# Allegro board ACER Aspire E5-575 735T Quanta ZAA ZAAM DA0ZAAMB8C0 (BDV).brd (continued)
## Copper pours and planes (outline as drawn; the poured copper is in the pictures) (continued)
SLEEVE on IN1 (solid shape): 206.3,27.2 206.3,24.66 206.18,24.53 205.42,24.53 205.16,24.78 205.16,27.2 205.29,27.32 206.18,27.32
SLEEVE_R on BOTTOM (solid shape): 206.56,24.02 206.56,22.63 206.43,22.5 205.42,22.5 205.29,22.63 205.29,24.15 206.43,24.15
SLEEVE_R on BOTTOM (solid shape): 210.29,15.38 210.35,15.38 210.39,15.37 210.4,15.33 210.4,15.3 211.59,15.3 211.62,15.29 211.64,15.25 211.64,15.05 211.62,15.01 211.59,15 210.4,15 210.4,14.8 211.59,14.8 211.62,14.79 211.64,14.75 211.64,14.55 211.62,14.51 211.59,14.5 210.4,14.5 210.4,14.3 211.59,14.3 211.62,14.29 211.64,14.25 211.64,14.05 211.62,14.01 211.59,14 210.4,14 210.4,13.99 209.1,13.99 208.84,14.24 208.84,15.13 209.1,15.39 210.29,15.39
SLEEVE_R on IN1 (solid shape): 206.69,23.51 206.69,21.74 206.56,21.61 205.67,21.61 205.67,23.51 205.8,23.64 206.56,23.64
SLEEVE_R on IN1 (solid shape): 209.86,15.26 209.86,14.24 209.73,14.12 208.46,14.12 208.08,14.5 208.08,15.13 208.46,15.51 209.61,15.51
SM_RCOMP_1 on IN1 (solid shape): 131.76,105.42 131.84,105.37 131.86,105.28 131.85,105.09 131.94,104.92 131.97,104.85 131.84,104.53 131.97,104.2 131.94,104.13 131.85,103.8 132.06,103.54 132.07,103.54 132.29,103.32 132.29,102.61 132.05,102.37 131.79,102.37 131.61,102.55 131.61,104.34 131.62,104.7 131.32,104.9 131.3,104.9 131.16,105.03 131.16,105.29 131.29,105.42
SYSTEM_AGND on TOP (solid shape): 57.54,40.07 57.54,38.39 57.49,38.2 57.54,38 57.54,37.28 57.37,37.12 57.06,37.12 56.85,37.39 56.85,37.59 56.84,37.6 56.84,37.73 56.58,37.99 56.3,37.99 56.18,38.1 56.18,39.65 55.05,40.79 55.05,41.24 55.12,41.32 56.29,41.32
TERM9 on TOP (solid shape): 26.07,92.53 26.07,78.46 25.91,78.3 25.05,78.3 24.87,78.48 24.87,89.33 24.24,89.96 24.24,92.86 24.39,93.01 25.58,93.01
TERM9 on BOTTOM (solid shape): 28.58,94.61 28.58,92.4 28.43,92.25 24.47,92.25 24.24,92.48 24.24,93.34 25.66,94.76 28.43,94.76
TP_PWR on TOP (solid shape): 116.74,171.34 119.83,171.34 120.01,171.16 120.01,169.92 119.84,169.74 118.52,169.74 118.21,170.06 118.19,170.07 118.18,170.07 118.16,170.09 117.66,170.09 117.65,170.07 116.39,170.07 116.13,169.82 115.63,169.82 115.4,170.05 115.4,171.42 115.45,171.47 116.62,171.47
TP_PWR on BOTTOM (solid shape): 119.36,170.63 119.36,170.35 119.31,170.3 119.31,170.05 120.14,169.22 119.96,169.04 119.15,169.85 118.98,169.68 119.78,168.87 119.6,168.69 118.78,169.52 118.72,169.52 118.27,169.97 118.27,170.14 118.75,170.62 118.75,170.61 118.88,170.73 119.26,170.73
USBPWR0 on TOP (solid shape): 23.86,26.18 23.86,26.05 23.3,25.5 23.3,24.15 21.52,22.37 21.27,22.37 20.63,21.74 19.82,21.74 19.78,21.78 19.67,21.86 19.53,21.89 19.52,21.89 19.47,21.93 19.47,21.95 19.39,22.1 19.26,22.2 19.23,22.21 19.23,22.55 19.28,22.63 19.37,22.64 19.87,23.04 19.31,23.35 19.22,23.35 19.17,23.44 19.17,23.95 19.17,24.26 19.08,24.34 19.08,24.36 19.07,24.36 19.07,24.5 19.1,24.53 19.45,24.53 19.45,24.52 20.69,24.52 20.69,24.53 21.39,24.53 21.52,24.66 21.52,24.81 21.53,24.91 21.52,25.01 21.52,25.8 22,26.28 23.75,26.28
USBPWR0 on IN2 (solid shape): outline of 417 points within 13.75,15.39 22.15,24.29
USBPWR1 on TOP (solid shape): 22.41,39.26 22.41,37.61 22.15,37.36 21.01,37.36 20.89,37.23 20.88,37.23 20.61,36.96 20.6,36.95 20.31,36.63 20.44,36.23 20.44,36.17 20.41,36.13 20,35.72 19.59,35.72 19.47,35.6 19.37,35.39 19.4,35.16 19.41,35.14 19.4,35.11 19.11,34.82 14.92,34.82 14.76,34.67 14.45,34.67 13.79,35.33 13.79,36.23 15.17,37.61 17.46,37.61 18.98,39.14 20.25,39.14 20.63,39.52 22.15,39.52
USBPWR1 on BOTTOM (solid shape): 16.06,35.45 16.06,33.42 15.61,32.98 15.33,32.98 15.16,33.15 15.16,33.54 15.42,33.8 15.42,35.45 15.55,35.58 15.93,35.58
USBPWRD2 on BOTTOM (solid shape): 212.15,27.83 212.15,26.82 211.89,26.56 211.89,25.04 212.78,24.15 212.78,21.23 212.53,20.97 211.72,20.97 211.7,21 210.4,21 210.38,20.97 209.61,20.97 209.35,21.23 207.57,21.23 207.5,21.3 211.7,21.3 211.7,21.5 210.4,21.5 210.4,21.3 207.5,21.3 207.19,21.61 207.19,21.8 211.7,21.8 211.7,22 210.4,22 210.4,21.8 207.19,21.8 207.19,22.3 211.7,22.3 211.7,22.5 210.4,22.5 210.4,22.3 207.19,22.3 207.19,26.56 207.45,26.82 209.1,26.82 209.35,27.07 209.35,27.83 209.48,27.96 212.02,27.96
V_BLIGHT on BOTTOM (solid shape): 117.15,165.85 117.15,163.85 117.06,163.76 115.58,163.76 115.34,163.52 115.34,163.43 115.12,163.21 113.85,163.21 113.72,163.34 113.72,164.23 114.48,164.99 114.48,165.91 115.07,166.5 115.79,166.5 116.6,165.69 116.78,165.86 115.97,166.67 115.79,166.5 115.07,166.5 115.5,166.92 116.07,166.92
VA on TOP (solid shape): 232.87,189.53 234.3,189.53 234.37,189.61 238.54,189.61 239.07,189.07 239.07,186.99 239.06,186.96 239.04,186.94 237.15,186.24 235.9,186.24 233.92,185.63 232.6,184 232.57,183.99 228.48,183.99 228.4,184.07 228.4,184.12 228.05,184.47 228.02,184.47 226.32,186.18 226.32,192.42 226.4,192.5 229.9,192.5
VA on BOTTOM (solid shape): 232.64,190.27 237.24,190.27 237.29,190.22 238.89,190.22 239.32,189.78 239.32,187.42 238.73,186.83 237.15,186.24 235.9,186.24 234.29,185.85 233.01,184.76 232.99,184.75 227.92,184.75 226.75,185.92 226.75,192.09 227.13,192.48 230.43,192.48
VA1 on BOTTOM (solid shape): 226.37,192.04 226.37,186.96 225.96,186.56 221.62,186.56 221.01,187.17 219.87,187.17 219.26,186.56 215.09,186.56 214.69,186.96 214.69,191.49 214.1,192.07 214.1,192.35 214.23,192.48 225.94,192.48
VA2 on BOTTOM (solid shape): 214.36,190.27 214.36,186.2 213.09,184.93 209.12,184.93 209.07,184.98 209.07,185.91 209.54,186.38 209.54,189.77 210.27,190.49 214.13,190.49
VCORE_PHASE on TOP (solid shape): 141.57,151.06 141.34,150.82 140.54,150.82 140.34,151.02 140.34,151.95 140.76,152.37 140.76,153.18 141.57,153.18
VCORE_PHASE on BOTTOM (solid shape): 142.83,163.27 142.83,162.48 140.93,160.57 140.39,160.57 140.35,160.59 140.34,160.62 140.34,161.08 140.35,161.12 140.39,161.13 140.42,161.13 141.84,162.55 141.84,163.24 141.92,163.32 142.78,163.32
VCORE_PHASE on BOTTOM (solid shape): 142.09,155.77 142.09,150.72 141.89,150.51 139.2,150.51 138.84,150.87 138.84,151.8 138.87,151.82 138.87,153.55 138.31,153.55 138.31,151.82 138.31,151.82 138.31,151.58 138,151.28 135.51,151.28 135.08,151.71 135.08,155.44 135.47,155.83 138.21,155.83 138.66,156.28 138.66,156.56 138.72,156.61 141.26,156.61
VCORE_VBST on BOTTOM (solid shape): 141.41,163.29 141.41,162.45 141.33,162.38 141.18,162.38 140.18,161.37 140.05,161.37 140.04,161.36 139.76,161.36 139.63,161.23 139.63,161.16 139.6,161.13 139.59,161.13 139.59,160.59 139.58,160.57 139.35,160.57 139.34,160.58 139.34,161.13 139.32,161.13 139.32,161.41 140.52,162.61 140.52,163.27 140.56,163.31 141.39,163.31
VCORE_VCC on TOP (solid shape): 137.88,161.18 137.88,160.27 137.55,159.94 136.12,159.94 136.05,160.01 136.05,160.85 136.11,160.92 137.01,160.92 137.01,161.11 137.29,161.39 137.67,161.39
VCORE_VCC on BOTTOM (solid shape): 138.18,160.67 138.18,160.45 138.17,160.41 138.13,160.4 137.62,160.4 137.62,160.15 138.13,160.15 138.17,160.14 138.18,160.1 138.18,159.95 138.17,159.91 138.13,159.9 137.61,159.9 137.61,159.87 137.57,159.84 136.07,159.84 136,159.91 136,160.9 136.4,161.31 137.55,161.31
N259399 on TOP (solid shape): 73.59,13.86 73.59,12.85 73.46,12.72 72.68,12.72 72.37,13.03 71.13,13.03 70.82,12.72 70.04,12.72 69.91,12.72 69.65,12.97 69.65,13.86 69.74,13.95 70.69,13.95 70.69,13.96 70.72,13.99 73.46,13.99
N16779422 on BOTTOM (solid shape): 134.24,16.99 134.24,16.2 134.25,16.18 134.26,16.16 134.38,16.04 134.39,16.02 134.4,16 134.4,14.72 134.4,14.7 134.41,14.69 134.53,14.56 134.55,14.55 134.57,14.55 135.29,14.55 135.31,14.54 135.33,14.53 135.36,14.5 135.37,14.48 135.37,14.46 135.37,13.52 135.37,13.5 135.36,13.48 135,13.13 133.15,13.13 133.13,13.13 133.11,13.14 132.87,13.39 132.87,16.36 132.87,16.38 132.86,16.39 132.67,16.59 132.67,17.04 132.82,17.19 134.04,17.19
N17002661 on BOTTOM (solid shape): 202.18,39.88 201.33,39.88 201.19,39.74 201.19,39.41 201.22,39.37 201.34,39.26 201.34,38.86 201.27,38.8 200.38,38.8 200.26,38.91 200.26,39.16 200.84,39.74 201.19,40.08 201.19,40.09 202.18,40.09
N17004316 on BOTTOM (solid shape): 192.82,49.45 192.82,47.35 192.36,46.9 191.89,46.9 191.84,46.95 191.84,47.92 191.91,47.99 191.91,48.6 191.86,48.66 191.73,48.66 191.73,48.66 191.06,48.66 191.06,49.93 192.34,49.93
N17047087 on TOP (solid shape): 176.64,178.33 176.64,174.39 175.57,173.32 175.55,173.32 175.47,173.25 168.1,173.25 167.98,173.12 167.95,173.12 166.2,171.37 165.77,171.37 164.71,170.31 164.17,170.31 164.09,170.24 163.99,170.21 163.92,170.28 163.17,170.43 163.46,169.72 163.47,169.72 163.49,169.71 163.5,169.67 163.49,169.63 163.45,169.6 163.45,168.24 162.39,167.18 158.27,167.18 157.99,167.46 157.99,170.05 158.58,170.63 158.58,171.81 163.1,176.33 165.06,176.33 166.07,177.35 169.47,177.35 170.17,178.05 171.38,178.05 171.94,178.61 176.36,178.61
N17047087 on BOTTOM (solid shape): 161.35,170.71 161.35,167.1 161.17,166.92 158.71,166.92 157.94,167.69 156.72,167.69 156.57,167.84 156.57,170.99 156.67,171.09 160.97,171.09
N17047087 on BOTTOM (solid shape): 176.59,178.2 176.59,175.52 175.46,174.39 175.46,174.05 174.83,173.43 168.92,173.43 168.85,173.49 168.85,176.97 170.07,178.19 170.08,178.19 170.53,178.63 176.15,178.63
N17047335 on BOTTOM (solid shape): 169.7,182.52 169.7,180.41 169.6,180.31 168.79,180.31 168.74,180.36 168.74,181.38 168.09,182.03 168.09,182.41 168.27,182.6 169.63,182.6
N17047399 on TOP (solid shape): 162.85,183.56 162.85,183.01 163.44,182.41 163.44,182.02 162.79,181.38 161.98,181.38 161.93,181.43 161.93,182.37 161.91,182.37 161.91,183.59 161.96,183.64 162.77,183.64
N17067635 on TOP (solid shape): 39.6,33.12 39.41,32.93 38.12,32.93 37.59,33.46 37.59,34.13 38.23,34.78 38.23,35.64 39.6,35.64
N17410561 on BOTTOM (solid shape): 58.48,96.41 58.48,94.76 58.73,94.51 58.73,90.65 58.45,90.37 54.08,90.37 54.06,90.34 53.42,90.34 53.09,90.67 53.09,93.24 52.51,93.82 52.51,96.67 52.76,96.92 57.97,96.92
N17410561 on BOTTOM (solid shape): 71.56,100.86 71.56,99.21 71.3,98.95 69.65,98.95 68.76,98.06 68.76,96.29 68.64,96.16 66.35,96.16 65.84,96.67 65.84,99.97 66.48,100.6 67.49,100.6 67.5,100.55 67.51,100.49 67.53,100.44 67.56,100.39 67.59,100.35 67.63,100.31 67.68,100.28 67.73,100.25 67.78,100.23 67.83,100.22 67.89,100.22 67.94,100.23 68,100.24 68.05,100.26 68.1,100.29 68.14,100.33 68.18,100.37 68.21,100.42 68.23,100.47 68.25,100.52 68.26,100.58 68.26,100.63 68.25,100.69 68.23,100.74 68.21,100.79 68.18,100.84 68.14,100.88 68.1,100.91 68.05,100.94 68,100.97 67.94,100.98 67.89,100.99 67.83,100.98 67.78,100.97 67.73,100.96 67.68,100.93 67.63,100.9 67.59,100.86 67.56,100.81 67.53,100.77 67.51,100.71 67.5,100.66 67.49,100.6 66.48,100.6 67.75,101.87 70.54,101.87
N17410561 on IN1 (solid shape): 70.54,100.35 70.54,99.08 68.13,96.67 60.41,96.67 59.67,95.92 59.63,95.91 59.57,95.89 59.52,95.86 59.47,95.83 59.43,95.78 59.4,95.73 59.37,95.68 59.36,95.64 58.1,94.38 54.79,94.38 54.54,94.63 54.54,97.94 57.23,100.63 67.52,100.63 67.52,100.58 67.53,100.52 67.54,100.47 67.57,100.43 67.6,100.38 67.63,100.34 67.67,100.31 67.72,100.28 67.77,100.26 67.82,100.25 67.87,100.25 67.93,100.25 67.98,100.26 68.03,100.28 68.08,100.31 68.12,100.34 68.15,100.38 68.18,100.43 68.21,100.47 68.22,100.52 68.23,100.58 68.23,100.63 68.22,100.68 68.21,100.73 68.18,100.78 68.15,100.83 68.12,100.87 68.08,100.9 68.03,100.93 67.98,100.94 67.93,100.96 67.87,100.96 67.82,100.96 67.77,100.94 67.72,100.93 67.67,100.9 67.63,100.87 67.6,100.83 67.57,100.78 67.54,100.73 67.53,100.68 67.52,100.63 57.23,100.63 57.84,101.24 69.65,101.24
N17410561 on IN2 (solid shape): 70.41,100.86 70.41,99.21 69.34,98.13 69.34,97.17 68.7,96.54 62.13,96.54 62.1,96.55 62.05,96.58 61.99,96.6 61.94,96.6 61.88,96.6 61.82,96.6 61.76,96.58 61.71,96.55 61.68,96.54 60.25,96.54 59.65,95.93 59.6,95.92 59.55,95.89 59.5,95.86 59.45,95.82 59.41,95.77 59.38,95.72 59.35,95.67 59.34,95.62 58.22,94.51 54.92,94.51 54.79,94.63 54.79,99.21 56.19,100.6 67.51,100.6 67.51,100.55 67.52,100.5 67.54,100.45 67.57,100.4 67.6,100.36 67.64,100.32 67.68,100.29 67.73,100.26 67.78,100.25 67.83,100.24 67.89,100.23 67.94,100.24 67.99,100.25 68.04,100.28 68.09,100.3 68.13,100.34 68.17,100.38 68.2,100.42 68.22,100.47 68.24,100.52 68.24,100.58 68.24,100.63 68.24,100.68 68.22,100.74 68.2,100.78 68.17,100.83 68.13,100.87 68.09,100.9 68.04,100.93 67.99,100.95 67.94,100.97 67.89,100.97 67.83,100.97 67.78,100.96 67.73,100.94 67.68,100.92 67.64,100.89 67.6,100.85 67.57,100.81 67.54,100.76 67.52,100.71 67.51,100.66 67.51,100.6 56.19,100.6 57.71,102.13 69.14,102.13
N17792405 on TOP (solid shape): 90.72,111.36 90.72,110.95 90.73,110.91 90.73,110.63 90.7,110.56 90.63,110.53 89.24,110.53 89.15,110.62 89.15,111.24 89.52,111.62 90.46,111.62
N19011701 on BOTTOM (solid shape): 59.04,84.86 59.04,84.25 58.93,84.14 56.7,84.14 56.66,84.19 56.66,84.99 56.67,85.01 58.88,85.01
N19940934 on TOP (solid shape): 51.52,43.96 51.52,43.2 51.42,43.1 50.96,43.1 50.73,42.87 50.73,41.75 50.63,41.65 49.84,41.65 49.74,41.75 49.74,43.71 50.12,44.09 51.39,44.09
N19941230 on TOP (solid shape): 50.42,35.5 50.42,34.69 50.76,34.36 51.09,34.36 51.14,34.31 51.14,33.37 51.11,33.34 49.98,33.34 49.34,33.98 49.34,35.44 49.45,35.55 50.37,35.55
N20965717 on BOTTOM (solid shape): 211.92,174.78 211.92,172.9 211.84,172.83 211.05,172.83 211,172.88 211,174.76 211.08,174.84 211.87,174.84
N20974305 on BOTTOM (solid shape): 165.12,51.24 165.12,50.41 165.32,50.21 166.26,50.21 166.46,50.01 166.46,48.76 166.34,48.64 164.01,48.64 163.89,48.76 163.89,51.1 164.12,51.33 165.03,51.33
N20974321 on BOTTOM (solid shape): 168.3,46.38 169.05,45.64 169.05,45.23 168.46,44.64 167.76,44.64 167.32,45.08 167.32,46.03 167.67,46.38 167.67,47.17 168.3,47.17
N20974337 on BOTTOM (solid shape): 169.55,49.75 169.55,47.43 169.41,47.29 169.1,47.29 168.44,47.95 167.67,47.95 167.62,48 167.62,49.75 167.75,49.88 169.42,49.88
N21057151 on TOP (solid shape): 38.33,49.58 40.14,49.58 40.24,49.47 40.24,48.91 40.01,48.69 38.31,48.69 38.28,48.66 37.06,48.66 36.73,48.33 36.73,47.39 36.61,47.26 35.62,47.26 35.49,47.39 35.49,50.29 35.54,50.34 37.57,50.34
N21057157 on TOP (solid shape): 47.94,52.06 47.94,47.77 47.81,47.64 46.95,47.64 45.83,48.76 43.87,48.76 43.82,48.81 43.82,49.47 43.87,49.52 45.62,49.52 46.41,50.31 46.46,50.35 46.5,50.4 46.81,50.71 46.81,51.87 47.07,52.14 47.86,52.14
N21057413 on BOTTOM (solid shape): 160.36,73.3 160.36,72.84 160.23,72.71 159.85,72.71 158.86,71.72 158.86,69.23 158.83,69.21 158.3,69.21 158.22,69.29 158.22,70.96 157.59,71.6 156.39,71.6 156.06,71.93 156.06,73.04 156.27,73.25 157.41,73.25 157.54,73.38 160.28,73.38
N21060883 on TOP (solid shape): 184.18,104.69 185.45,104.69 185.45,103.68 184.69,102.92 182.96,102.92 182.68,103.19 182.68,104.74 182.84,104.9 183.98,104.9
N21854704 on BOTTOM (solid shape): 208.59,52.6 208.54,52.6 207.69,51.75 207.25,51.75 206.92,52.08 206.92,52.11 206.91,52.17 206.89,52.22 206.89,53.18 207.57,53.87 208.59,53.87
N21854780 on BOTTOM (solid shape): 204.58,63.34 204.58,61.87 204.53,61.82 203.76,61.82 203.69,61.89 203.69,62.76 203.23,63.22 202.95,63.22 202.88,63.29 202.88,64.08 202.95,64.15 203.76,64.15
N21854821 on TOP (solid shape): 199.01,75.52 199.65,74.88 199.65,74.31 199.37,74.04 198.38,74.04 198.2,74.21 198.2,76.33 199.01,76.33
N21854867 on BOTTOM (solid shape): 195.08,61.14 195.08,60.35 195.05,60.28 194.98,60.25 194.97,60.24 194.12,60.24 193.93,60.06 193.1,60.06 193.1,61.12 193.48,61.51 194.71,61.51
N21854979 on TOP (solid shape): 191.38,72.3 191.38,71.22 191.3,71.14 189.16,71.14 189.08,71.22 189.08,72.03 189.82,72.77 190.91,72.77
N21854999 on BOTTOM (solid shape): 196.75,64.15 196.75,63.34 196.63,63.22 196.42,63.22 195.97,62.76 195.97,61.95 195.87,61.84 195.03,61.84 195,61.87 195,63.27 195.92,64.18 196.73,64.18
N21855085 on BOTTOM (solid shape): 207.57,56.96 207.57,54.63 206.56,54.63 206.56,55.9 206.59,55.93 206.59,56.39 206.46,56.51 206.46,56.97 206.55,57.06 207.48,57.06
N22411421 on BOTTOM (solid shape): 108.01,23.18 108.01,21.91 107.91,21.81 105.37,21.81 105.26,21.91 105.26,22.37 105.37,22.47 106.89,22.47 107.09,22.68 107.09,23.24 107.19,23.34 107.85,23.34
N22571742 on BOTTOM (solid shape): 190.82,37.43 190.82,36.94 191,36.76 191.31,36.76 191.49,36.58 191.49,36.28 190.87,36.28 190.68,36.47 189.85,36.47 189.74,36.58 189.74,36.83 189.89,36.97 189.89,36.98 190.41,37.5 190.75,37.5
N22668004 on BOTTOM (solid shape): 159.65,39.89 159.65,38.81 159.46,38.62 158.77,38.62 158.32,38.17 158.32,37.05 158.17,36.9 157.38,36.9 157.26,37.03 157.26,38.55 157.82,39.11 157.82,39.95 157.99,40.13 159.42,40.13
N22891363 on TOP (solid shape): 26.73,72.87 26.73,71.91 25.99,71.18 25.41,71.18 25.18,70.94 25.18,69.98 25.15,69.95 24.98,69.95 24.98,70.94 24.98,70.94 24.98,71.3 25.11,71.42 25.17,71.42 25.35,71.6 25.35,71.71 25.91,72.27 25.91,72.85 26.04,72.97 26.62,72.97
N23597706 on BOTTOM (solid shape): 137.78,184.78 137.85,184.75 137.88,184.68 137.88,184.38 137.88,184.35 137.87,184.33 137.87,183.45 137.68,183.26 137.01,183.26 136.73,183.54 136.73,184.33 137.18,184.78
N23599146 on BOTTOM (solid shape): 136.8,170.84 137.06,170.84 137.13,170.81 137.16,170.74 137.16,170.46 137.13,170.39 137.06,170.36 135.69,170.36 135.61,170.44 135.61,171.39 135.8,171.57 136.06,171.57
N23599619 on BOTTOM (solid shape): 143.57,184.5 143.57,183.71 143.16,183.31 141.94,183.31 141.94,184.17 142.17,184.4 142.17,184.68 142.2,184.75 142.27,184.78 143.29,184.78
N23602068 on TOP (solid shape): 141.41,155.32 141.41,154.55 141.66,154.3 141.66,153.54 141.59,153.46 140.65,153.46 140.52,153.59 140.52,154.22 140.14,154.6 140.14,155.21 140.29,155.37 141.36,155.37
N23602628 on BOTTOM (solid shape): 123.27,164.84 123.27,164.03 123.22,163.98 120.99,163.98 120.91,164.05 120.91,164.84 120.99,164.92 123.2,164.92
N23603098 on BOTTOM (solid shape): 131.53,164.71 131.53,163.88 131.45,163.8 130.13,163.8 130.13,163.83 129.13,163.83 129.06,163.9 129.06,164.74 129.14,164.82 131.43,164.82
N23603204 on BOTTOM (solid shape): 142.86,164.48 142.86,163.65 142.78,163.57 141.51,163.57 141.51,163.63 140.51,163.63 140.47,163.67 140.47,164.48 140.52,164.54 142.8,164.54
N23603328 on BOTTOM (solid shape): 127.75,162.91 127.75,162.45 128.71,161.49 128.71,160.78 128.46,160.78 128.46,161.33 128.32,161.48 127.48,161.48 127.08,161.88 127.08,162.93 127.24,163.09 127.58,163.09
N23605728 on TOP (solid shape): 150.88,154.96 150.88,154.01 150.51,153.64 150.51,153.27 150.44,153.19 149.62,153.19 149.52,153.3 149.52,155.05 149.62,155.15 150.69,155.15
N23605743 on BOTTOM (solid shape): 153.9,164.71 153.9,163.85 153.85,163.8 152.67,163.8 152.61,163.86 151.58,163.86 151.57,163.88 151.57,164.71 151.62,164.76 153.85,164.76
N24586737 on BOTTOM (solid shape): 68.92,77.9 68.92,76.32 68.81,76.22 67.93,76.22 67.87,76.27 67.87,77.11 67.44,77.54 67.44,78.46 67.52,78.53 68.28,78.53
N24592843 on BOTTOM (solid shape): 214.97,173.63 214.97,171.47 214.89,171.39 214.05,171.39 214,171.44 214,173.6 214.09,173.69 214.91,173.69
N24594676 on TOP (solid shape): 48.32,61.26 48.32,60.5 48.22,60.4 45.8,60.4 45.7,60.5 45.7,61.31 45.78,61.39 48.19,61.39
N245985901 on TOP (solid shape): 120.94,155.95 120.94,154.05 120.83,153.94 119.82,153.94 119.69,154.07 119.69,154.93 119.28,155.34 119.28,155.85 119.54,156.1 120.78,156.1
N245991371 on TOP (solid shape): 129.14,155.37 129.14,155.11 128.68,154.66 128.68,153.66 128.58,153.56 127.56,153.56 127.44,153.69 127.44,155.47 127.56,155.59 128.91,155.59

Small or netless copper shapes (teardrops, artwork), in the pictures only: 169 on TOP, 7 on BOTTOM, 2 on IN1, 277 on IN2, 2 on IN3

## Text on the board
Ref Des/Silkscreen Bottom: REV:C | DA0ZAAMB8C0 | MODEL:ZAA | X16
User.Comments: 244.9 | 198.7 | 31.0x37.0 | 33.0x37.0
Ref Des/Silkscreen Top: REV:C | DA0ZAAMB8C0 | X16
User.12: ADOGND | +5V_S5 | VIN | +5V | +VCCCORE | +VCCSA | GND | +VCCGT | +1.35V_GFX | +VGPU_CORE
User.28: ADOGND | GND
User.29: ADOGND | GND
User.45: FIGURE | TYPE | Oblong | Circle | SIZE | 57.0x24.0 | 59.0x28.0 | 63.0x24.0 | 69.0x39.0 | 71.0x31.0 | 82.0x39.0 | 91.0x28.0 | 94.0x39.0 | 102.0x31.0 | 146.0x87.0 | 10.0 | 12.0 | 14.0 | 16.0 | 22.0 | 24.0 | 28.0 | 32.0 | 35.0 | 118.0 | 126.0 | 134.0 | 140.0 | 161.0 | 256.0 | 31.0 | 37.0 | 39.0 | 41.0 | 43.0 | 47.0 | 55.0 | 63.0 | 67.0 | 87.0 | 217.0 | DRILL CHART: TOP to BOTTOM | ALL UNITS ARE IN MILS | PLATED | NON-PLATED | ROTATION | 0.000 | 90.000 | - | QTY | 2 | 4 | 1 | 29 | 6191 | 37 | 1332 | 12 | 19 | 83 | 44 | 18 | 8 | 6 | 5 | 3 | 7789 | TOTAL HOLES:
